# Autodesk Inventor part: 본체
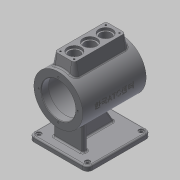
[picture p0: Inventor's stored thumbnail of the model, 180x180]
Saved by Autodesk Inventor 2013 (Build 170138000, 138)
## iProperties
Created: 2015-11
Part Number: 본체
Material: 알루미늄 6061
Document SubType Name: Modeling
Designer: mduedu
Density: 2.71 g/cm^3
Author: mduedu
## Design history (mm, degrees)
sketch "스케치2"
  geometry: C1 r 50 at (0, 0); 1 further point
  constraints: 1 centre point, 1 coincident
  dimensions: "d147" = 100 diameter of C1
extrude "돌출1" new body sketch "스케치2" stored distance "d12" = 130; taper "d13" = 0 deg
feature "쉘1" dims "d31" = 15, "d32" = 6, "d33" = 15
sketch "스케치5"
  geometry: C1 r 35 at (0, 0); 1 further point
  constraints: 1 centre point, 1 coincident
  dimensions: "d34" = 70 diameter of C1
extrude "돌출3" cut sketch "스케치5" stored distance "d36" = 3; taper "d37" = 0 deg
node "작업 평면1"
sketch "스케치6"
  geometry: L1 (-65, -60)-(65, -60); L2 (65, -60)-(65, 60); L3 (65, 60)-(-65, 60); L4 (-65, 60)-(-65, -60); L5 (-65, -60)-(65, 60); L6 (65, -60)-(-65, 60); 1 further point
  constraints: 12 end point, 2 midpoint, 2 parallel, 1 horizontal, 1 perpendicular
  dimensions: "d41" = 120 distance of L3.end L1.start; "d43" = 130 distance of L2.end L3.end
extrude "돌출4" join sketch "스케치6" distance "d44" = 10; taper "d45" = 0 deg
sketch "스케치19"
  geometry: L1 (-45, 30)-(-35, 30); L2 (-35, 30)-(-35, -30); L3 (-35, -30)-(-45, -30); L4 (-45, -30)-(-45, 30); L5 (-65, 60)-(-65, -60) reference; 2 further points
  constraints: 8 end point, 2 parallel, 1 horizontal, 1 horizontal alignment, 1 midpoint, 1 perpendicular
  dimensions: "d150" = 20 distance between parallel lines of L4 L5; "d151" = 10 distance of L1.start L1.end; "d152" = 60 distance of L3.end L1.start
extrude "돌출9" join sketch "스케치19" stored distance "d153" = 10; taper "d154" = 0 deg
sketch "스케치20"
  geometry: L1 (65, 35)-(50, 35) reference; L2 (50, 35)-(50, 44) reference; L3 (50, 44)-(-50, 44) reference; L4 (-50, 44)-(-50, 35) reference; L5 (-50, 35)-(-65, 35) reference; L6 (-65, 35)-(-65, 50) reference; L7 (-65, 50)-(65, 50) reference; L8 (65, 50)-(65, 35) reference; L9 (50, -35)-(65, -35) reference; L10 (65, -35)-(65, -50) reference; L11 (65, -50)-(45, -50) reference; L12 (45, -50)-(45, -90) reference; L13 (45, -90)-(65, -90) reference; L14 (65, -90)-(65, -100) reference; L15 (65, -100)-(-65, -100) reference; L16 (-65, -100)-(-65, -90) reference; L17 (-65, -90)-(35, -90) reference; L18 (35, -90)-(35, -50) reference; L19 (35, -50)-(-65, -50) reference; L20 (-65, -50)-(-65, -35) reference; L21 (-65, -35)-(-50, -35) reference; L22 (-50, -35)-(-50, -44) reference; L23 (-50, -44)-(50, -44) reference; L24 (50, -44)-(50, -35) reference; L25 (-45, -90)-(-21.906, -50); 1 further point
  constraints: 2 end point, 2 point on line
  dimensions: "d155" = 20 distance from line of L25.start L16; "d156" = 120 deg angle of L25 L17
feature "리브2" sketch "스케치20" dims "d157" = 1, "d158" = 10, "d159" = 0, "d160" = 0, "d161" = 1, "d162" = 1
fillet "모깎기21" dims "d163" = 3
fillet "모깎기22" dims "d164" = 3
fillet "모깎기23" dims "d165" = 3
sketch "스케치21" dims "d166" = 80
  geometry: 3 further points
  constraints: 2 horizontal alignment, 1 coincident, 2 other
hole "구멍6" sketch "스케치21" at (40, 0) diameter "d168" = 3.242; stored, may be unused: countersink angle "d172" = 90 deg, drill point angle "d174" = 118 deg; dims "d169" = 9, "d170" = 4, "d171" = 2, "d173" = 11
node "작업 평면2"
sketch "스케치13"
  geometry: L1 (-52.5, -20)-(52.5, -20); L2 (52.5, -20)-(52.5, 20); L3 (52.5, 20)-(-52.5, 20); L4 (-52.5, 20)-(-52.5, -20); L5 (-52.5, -20)-(52.5, 20); L6 (52.5, -20)-(-52.5, 20); 1 further point
  constraints: 12 end point, 2 midpoint, 2 parallel, 1 horizontal, 1 perpendicular
  dimensions: "d93" = 105 distance of L2.end L3.end; "d95" = 40 distance of L1.end L2.end
extrude "돌출8" join sketch "스케치13" stored distance "d96" = 80; taper "d97" = 0 deg
fillet "모깎기15" dims "d98" = 5
feature "면 기울기1" dims angle "d178" = 10 deg
fillet "모깎기24" dims "d179" = 3
sketch "스케치14"
  geometry: L1 (-52.5, 15)-(-52.5, -15) reference; L2 (52.5, -15)-(52.5, 15) reference; L3 (-52.5, 0)-(52.5, 0); 4 further points
  constraints: 2 end point, 2 midpoint, 2 point on line, 1 coincident
  dimensions: "d100" = 32 distance of point (-32, 0) point (0, 0); "d102" = 32 distance of point (32, 0) point (0, 0) (derived)
hole "구멍3" sketch "스케치14" at (-32, 0), (0, 0), (32, 0) diameter "d103" = 22; stored, may be unused: countersink angle "d107" = 90 deg, drill point angle "d109" = 118 deg; dims "d104" = 8, "d105" = 28, "d106" = 5, "d108" = 10
sketch "스케치15"
  geometry: L1 (46.5, -14)-(-46.5, -14); L2 (-46.5, -14)-(-46.5, 14); L3 (-46.5, 14)-(46.5, 14); L4 (46.5, 14)-(46.5, -14); L5 (46.5, -14)-(-46.5, 14); L6 (-46.5, -14)-(46.5, 14); L7 (47.5, 20)-(-47.5, 20) reference; L8 (-52.5, 15)-(-52.5, -15) reference; 5 further points
  constraints: 12 end point, 4 coincident, 2 midpoint, 2 parallel, 1 horizontal, 1 perpendicular
  dimensions: "d110" = 6 distance between parallel lines of L3 L7; "d111" = 6 distance between parallel lines of L2 L8
hole "구멍4" sketch "스케치15" at (-46.5, 14), (46.5, 14), (46.5, -14), (-46.5, -14) diameter "d112" = 3.242; stored, may be unused: countersink angle "d116" = 90 deg, drill point angle "d118" = 118 deg; dims "d113" = 10, "d114" = 28, "d115" = 5, "d117" = 13
node "작업 평면3"
sketch "스케치22"
  geometry: 2 further points
  constraints: 1 coincident, 1 other
feature "엠보싱3" sketch "스케치22" dims "d32" = 6, "d181" = 0.5, "d182" = 0
chamfer "모따기2" distance "d183" = 1; stored, may be unused: second distance "d184" = 2, angle "d185" = 45 deg
fillet "모깎기25" dims "d186" = 10
sketch "스케치23"
  geometry: L1 (55, 60)-(-55, 60) reference; L2 (65, -50)-(65, 50) reference; L3 (-55, -60)-(55, -60) reference; L4 (-65, 50)-(-65, -50) reference; A1 r 10 centre (-55, 50) between (-55, 60) and (-65, 50) reference; A2 r 10 centre (55, 50) between (65, 50) and (55, 60) reference; A3 r 10 centre (55, -50) between (55, -60) and (65, -50) reference; A4 r 10 centre (-55, -50) between (-65, -50) and (-55, -60) reference; 1 further point
hole "구멍7" sketch "스케치23" at (-55, 50), (-55, -50), (55, -50), (55, 50) diameter "d187" = 6; stored, may be unused: countersink angle "d191" = 90 deg, drill point angle "d193" = 118 deg; dims "d188" = 9, "d189" = 10, "d190" = 2, "d192" = 11
fillet "모깎기26" dims "d194" = 3
node "솔리드1"
pattern_circular "원형 패턴2" dims angle "d176" = 360 deg
mirror "대칭5"
node "투영된 루프2"
node "절단 모서리 투영1"
